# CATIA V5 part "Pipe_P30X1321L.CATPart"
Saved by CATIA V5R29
Part number: Pipe_P30X1321L
Source: Unknown
Bounding box of the stored display mesh (mm): x -14.936 to 14.936, y -15 to 15, z -1321 to 0
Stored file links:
  C:\가치같이\SmartFactory_BoxErectorConveyor\Boxing(under)\Pipe_P30X1321L.CATPart
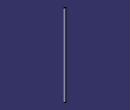
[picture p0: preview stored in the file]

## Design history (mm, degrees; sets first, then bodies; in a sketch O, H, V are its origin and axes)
Body1 (main body)
  Solid1 "PartBody": solid without history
